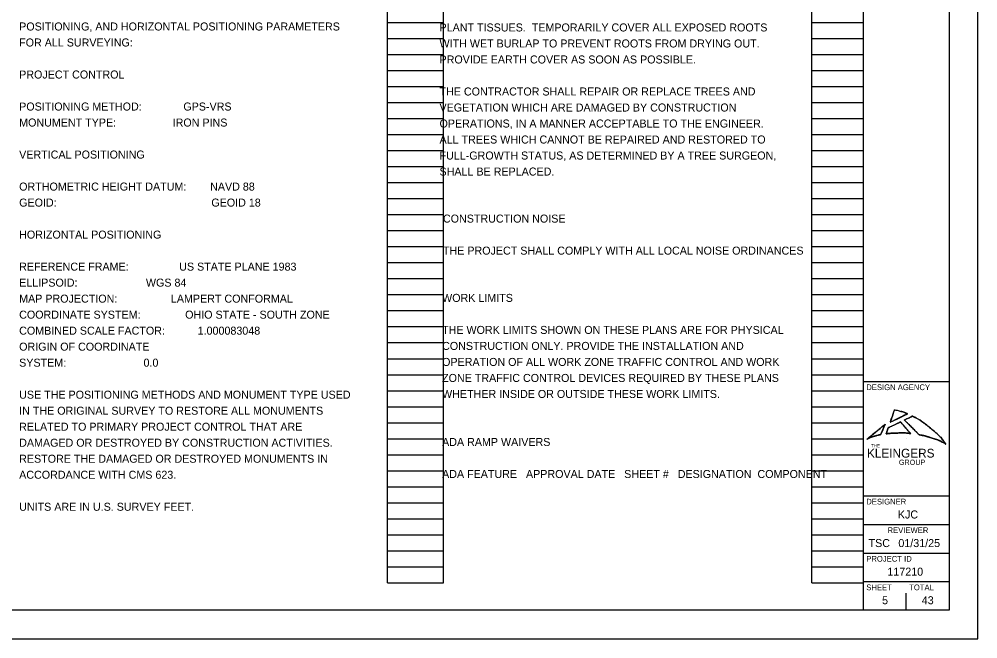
# Model space of a CAD drawing. Extents: x -7.5 to 43.2, y 0 to 22.
# Drawn here: x 17.24 to 34, y 0 to 10.84 of the extents above; entities that cross this region are included whole.
import ezdxf

# ---------------------------------------------------------------- set-up
doc = ezdxf.new("R2010")
doc.units = 0
for name, color, linetype in [('SH_Border', 7, 'Continuous'), ('SH_Cut_Line', 7, 'Continuous'), ('SH_Data', 7, 'Continuous'), ('SH_Text', 7, 'Continuous')]:
    doc.layers.add(name, color=color, linetype=linetype)

msp = doc.modelspace()

# ---------------------------------------------------------------- linework, layer by layer
at = {"layer": 'SH_Border'}
for p, q in [((32, 0.5), (32, 21.5)), ((32, 4.5), (33.5, 4.5)), ((32, 2.5), (33.5, 2.5)), ((32, 2), (33.5, 2)), ((32, 1.5), (33.5, 1.5)), ((32, 1), (33.5, 1))]:
    msp.add_line(p, q, dxfattribs=at)
msp.add_lwpolyline([(1.5, 21.5), (33.5, 21.5), (33.5, 0.5), (1.5, 0.5)], close=True, dxfattribs=at)
at = {"layer": 'SH_Cut_Line'}
msp.add_lwpolyline([(0, 0), (34, 0), (34, 22), (0, 22)], close=True, dxfattribs=at)
at = {"layer": 'SH_Data'}
for p, q in [((23.68, 0.98), (23.68, 21.14)), ((24.66, 0.98), (24.66, 21.14)), ((31.1, 0.98), (31.1, 21.14)), ((32, 0.98), (32, 21.14)), ((23.68, 10.78), (24.66, 10.78)), ((31.1, 10.78), (32, 10.78)), ((23.68, 10.5), (24.66, 10.5)), ((31.1, 10.5), (32, 10.5)), ((23.68, 10.22), (24.66, 10.22)), ((31.1, 10.22), (32, 10.22)), ((23.68, 9.94), (24.66, 9.94)), ((31.1, 9.94), (32, 9.94)), ((23.68, 9.66), (24.66, 9.66)), ((31.1, 9.66), (32, 9.66)), ((23.68, 9.38), (24.66, 9.38)), ((31.1, 9.38), (32, 9.38)), ((23.68, 9.1), (24.66, 9.1)), ((31.1, 9.1), (32, 9.1)), ((23.68, 8.82), (24.66, 8.82)), ((31.1, 8.82), (32, 8.82)), ((23.68, 8.54), (24.66, 8.54)), ((31.1, 8.54), (32, 8.54)), ((23.68, 8.26), (24.66, 8.26)), ((31.1, 8.26), (32, 8.26)), ((23.68, 7.98), (24.66, 7.98)), ((31.1, 7.98), (32, 7.98)), ((23.68, 7.7), (24.66, 7.7)), ((31.1, 7.7), (32, 7.7)), ((23.68, 7.42), (24.66, 7.42)), ((31.1, 7.42), (32, 7.42)), ((23.68, 7.14), (24.66, 7.14)), ((31.1, 7.14), (32, 7.14)), ((23.68, 6.86), (24.66, 6.86)), ((31.1, 6.86), (32, 6.86)), ((23.68, 6.58), (24.66, 6.58)), ((31.1, 6.58), (32, 6.58)), ((23.68, 6.3), (24.66, 6.3)), ((31.1, 6.3), (32, 6.3)), ((23.68, 6.02), (24.66, 6.02)), ((31.1, 6.02), (32, 6.02)), ((23.68, 5.74), (24.66, 5.74)), ((31.1, 5.74), (32, 5.74)), ((23.68, 5.46), (24.66, 5.46)), ((31.1, 5.46), (32, 5.46)), ((23.68, 5.18), (24.66, 5.18)), ((31.1, 5.18), (32, 5.18)), ((23.68, 4.9), (24.66, 4.9)), ((31.1, 4.9), (32, 4.9)), ((23.68, 4.62), (24.66, 4.62)), ((31.1, 4.62), (32, 4.62)), ((23.68, 4.34), (24.66, 4.34)), ((31.1, 4.34), (32, 4.34)), ((23.68, 4.06), (24.66, 4.06)), ((31.1, 4.06), (32, 4.06)), ((23.68, 3.78), (24.66, 3.78)), ((31.1, 3.78), (32, 3.78)), ((23.68, 3.5), (24.66, 3.5)), ((31.1, 3.5), (32, 3.5)), ((32.75, 3.5), (32.75, 3.5)), ((23.68, 3.22), (24.66, 3.22)), ((31.1, 3.22), (32, 3.22)), ((23.68, 2.94), (24.66, 2.94)), ((31.1, 2.94), (32, 2.94)), ((23.68, 2.66), (24.66, 2.66)), ((31.1, 2.66), (32, 2.66)), ((23.68, 2.38), (24.66, 2.38)), ((31.1, 2.38), (32, 2.38)), ((23.68, 2.1), (24.66, 2.1)), ((31.1, 2.1), (32, 2.1)), ((23.68, 1.82), (24.66, 1.82)), ((31.1, 1.82), (32, 1.82)), ((23.68, 1.54), (24.66, 1.54)), ((31.1, 1.54), (32, 1.54)), ((23.68, 1.26), (24.66, 1.26)), ((31.1, 1.26), (32, 1.26)), ((23.68, 0.98), (24.66, 0.98)), ((31.1, 0.98), (32, 0.98)), ((32.375, 0.675), (32.375, 0.675)), ((32.75, 0.5), (32.75, 0.8))]:
    msp.add_line(p, q, dxfattribs=at)
at = {"layer": 'SH_Text'}
for points, degree in [([(32.47, 3.788), (32.47, 3.788), (32.772, 3.935), (32.772, 3.935)], 2), ([(32.542, 4.004), (32.542, 4.004), (32.47, 3.788), (32.47, 3.788)], 2), ([(32.772, 3.935), (32.772, 3.935), (32.722, 3.958), (32.655, 3.979), (32.588, 3.999), (32.542, 4.004), (32.542, 4.004), (32.542, 4.004), (32.47, 3.788), (32.47, 3.788), (32.47, 3.788), (32.772, 3.935), (32.772, 3.935)], 3), ([(32.772, 3.935), (32.772, 3.935), (32.722, 3.958), (32.655, 3.979)], 2), ([(33.2, 3.512), (33.079, 3.551), (32.978, 3.567), (32.978, 3.567), (32.978, 3.567), (32.717, 3.827), (32.717, 3.827), (32.717, 3.827), (32.855, 3.894), (32.855, 3.894), (32.855, 3.894), (32.985, 3.834), (33.142, 3.708), (33.348, 3.542), (33.439, 3.405), (33.439, 3.405), (33.439, 3.405), (33.351, 3.463), (33.2, 3.512)], 3), ([(32.717, 3.827), (32.717, 3.827), (32.855, 3.894), (32.855, 3.894)], 2), ([(32.855, 3.894), (32.855, 3.894), (32.985, 3.834), (33.142, 3.708)], 2), ([(32.379, 3.752), (32.379, 3.752), (32.062, 3.492), (32.062, 3.492)], 2), ([(32.379, 3.752), (32.379, 3.752), (32.062, 3.492), (32.062, 3.492), (32.062, 3.492), (32.133, 3.529), (32.21, 3.55), (32.28, 3.569), (32.303, 3.572), (32.303, 3.572), (32.303, 3.572), (32.379, 3.752), (32.379, 3.752)], 3), ([(32.303, 3.572), (32.303, 3.572), (32.379, 3.752), (32.379, 3.752)], 2), ([(32.648, 3.793), (32.648, 3.793), (32.83, 3.589), (32.83, 3.589), (32.83, 3.589), (32.734, 3.604), (32.602, 3.6), (32.455, 3.595), (32.396, 3.584), (32.396, 3.584), (32.396, 3.584), (32.434, 3.691), (32.434, 3.691), (32.434, 3.691), (32.648, 3.793), (32.648, 3.793)], 3), ([(32.396, 3.584), (32.396, 3.584), (32.434, 3.691), (32.434, 3.691)], 2), ([(32.434, 3.691), (32.434, 3.691), (32.648, 3.793), (32.648, 3.793)], 2), ([(32.648, 3.793), (32.648, 3.793), (32.83, 3.589), (32.83, 3.589)], 2), ([(32.978, 3.567), (32.978, 3.567), (32.717, 3.827), (32.717, 3.827)], 2), ([(33.142, 3.708), (33.348, 3.542), (33.439, 3.405), (33.439, 3.405)], 2), ([(32.062, 3.492), (32.062, 3.492), (32.133, 3.529), (32.21, 3.55)], 2), ([(32.21, 3.55), (32.28, 3.569), (32.303, 3.572), (32.303, 3.572)], 2), ([(32.602, 3.6), (32.455, 3.595), (32.396, 3.584), (32.396, 3.584)], 2), ([(32.83, 3.589), (32.83, 3.589), (32.734, 3.604), (32.602, 3.6)], 2), ([(33.2, 3.512), (33.079, 3.551), (32.978, 3.567), (32.978, 3.567)], 2), ([(33.439, 3.405), (33.439, 3.405), (33.351, 3.463), (33.2, 3.512)], 2)]:
    msp.add_open_spline(points, degree=degree, dxfattribs=at)

# ---------------------------------------------------------------- texts
at = {"layer": 'SH_Data'}
for s, height, p in [('DESIGN AGENCY', 0.1, (32.05, 4.35)), ('DESIGNER', 0.1, (32.05, 2.35)), ('KJC', 0.14, (32.602, 2.105)), ('REVIEWER', 0.1, (32.422, 1.85)), ('TSC', 0.14, (32.09, 1.605)), ('01/31/25', 0.14, (32.611, 1.605)), ('PROJECT ID', 0.1, (32.05, 1.35)), ('117210', 0.14, (32.419, 1.105)), ('SHEET', 0.1, (32.05, 0.85)), ('TOTAL', 0.1, (32.8, 0.85)), ('5', 0.14, (32.326, 0.605)), ('43', 0.14, (33.02, 0.605))]:
    msp.add_text(s, height=height, dxfattribs=at).set_placement(p)
at = {"layer": 'SH_Text'}
for s, height, p in [('POSITIONING, AND HORIZONTAL POSITIONING PARAMETERS', 0.14, (17.24, 10.64)), ('PLANT TISSUES.  TEMPORARILY COVER ALL EXPOSED ROOTS ', 0.14, (24.589, 10.623)), ('FOR ALL SURVEYING:', 0.14, (17.24, 10.36)), ('WITH WET BURLAP TO PREVENT ROOTS FROM DRYING OUT.  ', 0.14, (24.589, 10.343)), ('PROVIDE EARTH COVER AS SOON AS POSSIBLE.', 0.14, (24.589, 10.063)), ('PROJECT CONTROL', 0.14, (17.24, 9.8)), ('THE CONTRACTOR SHALL REPAIR OR REPLACE TREES AND ', 0.14, (24.589, 9.503)), ('POSITIONING METHOD:              GPS-VRS', 0.14, (17.24, 9.24)), ('VEGETATION WHICH ARE DAMAGED BY CONSTRUCTION ', 0.14, (24.589, 9.223)), ('MONUMENT TYPE:                   IRON PINS', 0.14, (17.24, 8.96)), ('OPERATIONS, IN A MANNER ACCEPTABLE TO THE ENGINEER.  ', 0.14, (24.589, 8.943)), ('ALL TREES WHICH CANNOT BE REPAIRED AND RESTORED TO ', 0.14, (24.589, 8.663)), ('VERTICAL POSITIONING', 0.14, (17.24, 8.4)), ('FULL-GROWTH STATUS, AS DETERMINED BY A TREE SURGEON, ', 0.14, (24.589, 8.383)), ('SHALL BE REPLACED.', 0.14, (24.589, 8.103)), ('ORTHOMETRIC HEIGHT DATUM:        NAVD 88', 0.14, (17.24, 7.84)), ('GEOID:                         ', 0.14, (17.24, 7.56)), ('GEOID 18', 0.14, (20.6, 7.56)), ('CONSTRUCTION NOISE', 0.14, (24.649, 7.28)), ('HORIZONTAL POSITIONING', 0.14, (17.24, 7)), ('THE PROJECT SHALL COMPLY WITH ALL LOCAL NOISE ORDINANCES', 0.14, (24.649, 6.72)), ('REFERENCE FRAME:                 US STATE PLANE 1983', 0.14, (17.24, 6.44)), ('ELLIPSOID:                       WGS 84', 0.14, (17.24, 6.16)), ('WORK LIMITS', 0.14, (24.634, 5.893)), ('MAP PROJECTION:                  LAMPERT CONFORMAL', 0.14, (17.24, 5.88)), ('COORDINATE SYSTEM:               OHIO STATE - SOUTH ZONE', 0.14, (17.24, 5.6)), ('COMBINED SCALE FACTOR:           1.000083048', 0.14, (17.24, 5.32)), ('THE WORK LIMITS SHOWN ON THESE PLANS ARE FOR PHYSICAL', 0.14, (24.634, 5.333)), ('ORIGIN OF COORDINATE', 0.14, (17.24, 5.04)), ('CONSTRUCTION ONLY. PROVIDE THE INSTALLATION AND', 0.14, (24.634, 5.053)), ('SYSTEM:                          0.0', 0.14, (17.24, 4.76)), ('OPERATION OF ALL WORK ZONE TRAFFIC CONTROL AND WORK', 0.14, (24.634, 4.773)), ('ZONE TRAFFIC CONTROL DEVICES REQUIRED BY THESE PLANS', 0.14, (24.634, 4.493)), ('USE THE POSITIONING METHODS AND MONUMENT TYPE USED', 0.14, (17.24, 4.2)), ('WHETHER INSIDE OR OUTSIDE THESE WORK LIMITS.', 0.14, (24.634, 4.213)), ('IN THE ORIGINAL SURVEY TO RESTORE ALL MONUMENTS', 0.14, (17.24, 3.92)), ('RELATED TO PRIMARY PROJECT CONTROL THAT ARE', 0.14, (17.24, 3.64)), ('DAMAGED OR DESTROYED BY CONSTRUCTION ACTIVITIES.', 0.14, (17.24, 3.36)), ('ADA RAMP WAIVERS', 0.14, (24.634, 3.373)), ('THE', 0.0561, (32.135, 3.349)), ('RESTORE THE DAMAGED OR DESTROYED MONUMENTS IN', 0.14, (17.24, 3.08)), ('KLEINGERS', 0.1542, (32.062, 3.17)), ('GROUP', 0.0911, (32.62, 3.042)), ('ACCORDANCE WITH CMS 623.', 0.14, (17.24, 2.8)), ('ADA FEATURE   APPROVAL DATE   SHEET #   DESIGNATION  COMPONENT', 0.14, (24.634, 2.813)), ('UNITS ARE IN U.S. SURVEY FEET.', 0.14, (17.24, 2.24))]:
    msp.add_text(s, height=height, dxfattribs=at).set_placement(p)

doc.saveas('drawing.dxf')
